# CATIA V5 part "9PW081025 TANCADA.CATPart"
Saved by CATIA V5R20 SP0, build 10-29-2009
Part number: 9PW081025 TANCADA
Revision: ANY
Definition: UNKNOWN
Nomenclature: 9PW081025 TANCADA
Source: Unknown
Bounding box of the stored display mesh (mm): x -140 to 0, y -7 to 4.5, z -5.1 to 5.1
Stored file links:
  C:\Users\Utente\Desktop\IO LAVORO\3D X SITO CF\CUMSA\3D files PW\pw081025\pw081025_injection\9PW081025 TANCADA.CATPart
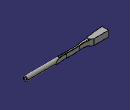
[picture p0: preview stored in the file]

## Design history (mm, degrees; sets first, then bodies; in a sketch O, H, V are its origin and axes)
Body1 "Chaflán2" (main body)
  Solid1: solid without history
